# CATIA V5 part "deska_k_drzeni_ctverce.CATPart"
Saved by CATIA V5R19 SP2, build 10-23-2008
Part number: Part3
Bounding box of the stored display mesh (mm): x 0 to 20, y -80 to 80, z -80 to 80
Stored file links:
  C:\Users\Martiin\Desktop\9.semestr\Projekt-diplomka\3D model\deska_k_drzeni_ctverce.CATPart
  C:\Users\Martiin\Desktop\9.semestr\Projekt-diplomka\3D model\ctverec_naklapeni_vetsi.CATPart
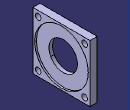
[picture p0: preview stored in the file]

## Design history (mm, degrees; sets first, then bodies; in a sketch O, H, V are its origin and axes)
Body1 (main body)
  Sketch1 on yz-plane, origin (0, 0, 0), H (0, 1, 0), V (0, 0, 1)
    line L1 (-80, 80) -> (80, 80)
    line L2 (80, 80) -> (80, -80)
    line L3 (80, -80) -> (-80, -80)
    line L4 (-80, -80) -> (-80, 80)
    distance L1 H = 80
    distance L3 L1 = 160
    distance L4 V = 80
    distance L4 L2 = 160
    horizontal: L1 H, L3 H
    vertical: L2 V, L4 V
  Pad1: profile Sketch1, direction (1, 0, 0), length 20
  Sketch2 on end face of Pad1, origin (20, 0, 0), H (0, 1, 0), V (0, 0, 1)
  Sketch3 on end face of Pad1, origin (20, 3.9667, 44.8632), H (0, 1, 0), V (0, 0, 1)
    point P1 (-68.9667, 20.1368)
    reference projected line E1 (76.0333, 35.1368) -> (-83.9667, 35.1368) from edge [face of Pad1 from Sketch1.L1 | end face of Pad1]
    reference projected line E2 (-83.9667, 35.1368) -> (-83.9667, -124.8632) from edge [face of Pad1 from Sketch1.L4 | end face of Pad1]
    distance P1 E1 = 15
    distance E2 P1 = 15
  Hole1: placed by Sketch3, at (20, -65, 65) direction (-1, 0, 0), diameter 16, through (limit type 6)
  RectPattern1: of Hole1, direction 1 instances 2, spacing 130, along face of Pad1 from Sketch1.L1
  RectPattern2: of RectPattern1, direction 1 instances 2, spacing 130, along face of Pad1 from Sketch1.L4
  Sketch4 on end face of Pad1, origin (20, 0, 0), H (0, 1, 0), V (0, 0, 1)
    circle A1 centre (0, 0) radius 75
    radius A1 = 75
  Pocket1: profile Sketch4, direction (-1, 0, 0), length 5
  Sketch5 on start face of Pad1, origin (0, 0, 0), H (0, -1, 0), V (0, 0, 1)
    circle A1 centre (0, 0) radius 40
    radius A1 = 40
  Pocket2: profile Sketch5, direction (1, 0, 0), length 5
  Sketch6 on face of Pad1, origin (0, 0, 0), H (0, -1, 0), V (0, 0, 1)
    circle A1 centre (0, 0) radius 60
    point P1 (0, 60)
    radius A1 = 60
    coincidence: A1 P1, P1 V
  Pocket3: profile Sketch6, direction (1, 0, 0), length 5
  Sketch7 on face of Pocket3, origin (5, 0, 0), H (0, -1, 0), V (0, 0, 1)
    point P1 (0, 0)
    coincidence: P1 O
  Sketch8 on face of Pocket3, origin (5, 0, 0), H (0, 1, 0), V (0, 0, -1)
    point P1 (0, 0)
    reference projected point E1 (0, 0) from Sketch7.P1
    coincidence: E1 P1
  Hole2: placed by Sketch8, at (5, 0, 0) direction (1, 0, 0), diameter 80, through (limit type 6)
